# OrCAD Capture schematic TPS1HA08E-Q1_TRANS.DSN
size Custom; title: TPS1HA08E-Q1: 40-V, 8-mOhm Single-Channel Smart; rev: 1.0; note: Datasheet: SLVSDM4D     EVM: SLVUBA6; note: High-Side Switch
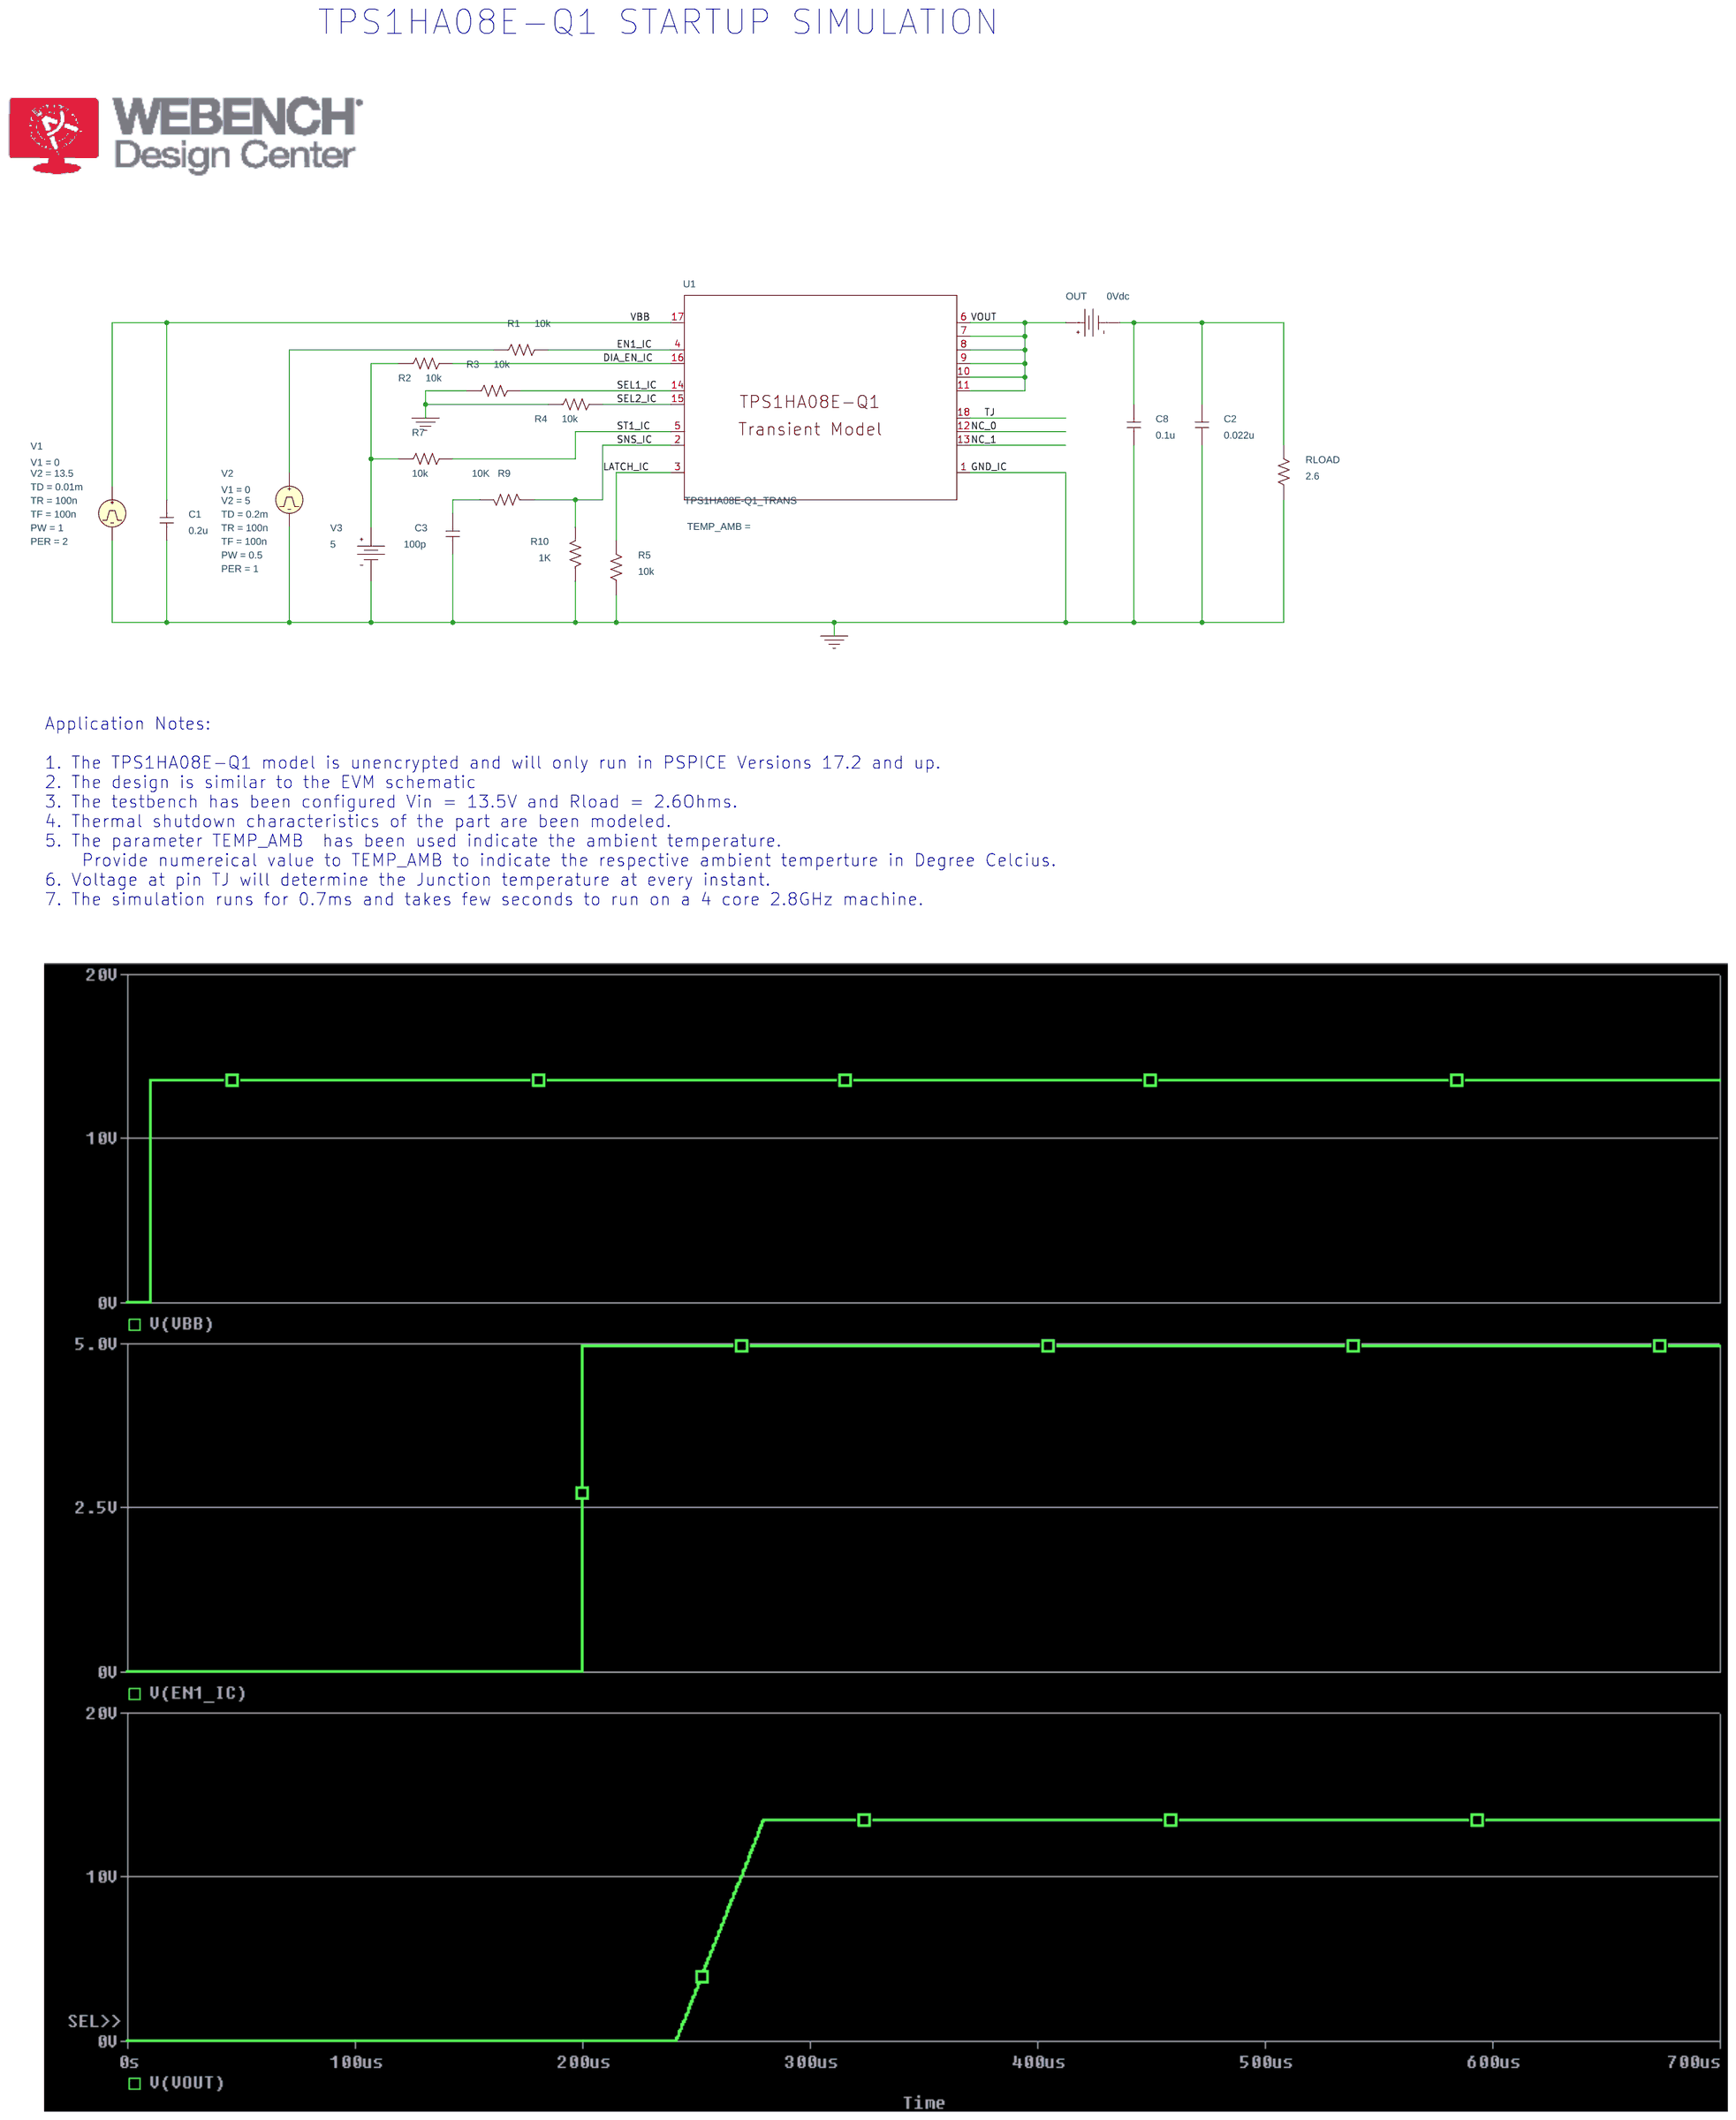
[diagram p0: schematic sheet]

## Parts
C1  0.2u  [RAD/CK05]
C2  0.022u  [RAD/CK05]
C3  100p  [RAD/CK05]
C8  0.1u  [RAD/CK05]
OUT  VDC
R1  10k  [AX/RC05]
R2  10k  [AX/RC05]
R3  10k  [AX/RC05]
R4  10k  [AX/RC05]
R5  10k  [AX/RC05]
R7  10k  [AX/RC05]
R9  10K  [AX/RC05]
R10  1K  [AX/RC05]
RLOAD  2.6  [AX/RC05]
U1  TPS1HA08E-Q1_TRANS  [PWP0016M_N]
V1  VPULSE
V2  VPULSE
V3  VDC

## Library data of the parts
C1-C3 C8 = C
OUT = VDC: DC: 0Vdc
R1-R5 R7 R9 R10 RLOAD = R
U1 = TPS1HA08E-Q1_TRANS: PSpiceTemplate: X^@REFDES  %DIA_EN %EN %GND %LATCH %NC_0 %NC_1 %SEL1 %SEL2 %SNS %ST %TJ %VBB %VOUT_0 %VOUT_1 %VOUT_2 %VOUT_3 %VOUT_4 %VOUT_5 @MODEL PARAMS: ?TEMP_AMB|TEMP_AMB=@TEMP_AMB||TEMP_AMB=25|
V1 = VPULSE: PER: 2; PW: 1; TD: 0.01m; TF: 100n; TR: 100n; V1: 0; V2: 13.5
V2 = VPULSE: PER: 1; PW: 0.5; TD: 0.2m; TF: 100n; TR: 100n; V1: 0; V2: 5
V3 = VDC: DC: 5

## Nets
0: C1.2 C2.2 C3.2 C8.2 R3.1 R4.1 R5.1 R10.1 RLOAD.1 U1.1(GND) V1.2(-) V2.2(-) V3.1(-)
DIA_EN_IC: R2.2 U1.16(DIA_EN)
EN1_IC: R1.2 U1.4(EN)
LATCH_IC: R9.1 R10.2 U1.2(SNS)
NC_0: U1.12(NC_0)
NC_1: U1.13(NC_1)
SEL1_IC: R3.2 U1.14(SEL1)
SEL2_IC: R4.2 U1.15(SEL2)
ST1_IC: R7.2 U1.5(ST)
TJ: U1.18(TJ)
VBB: C1.1 U1.17(VBB) V1.1(+)
VOUT: OUT.0(+) U1.6(VOUT_0) U1.7(VOUT_1) U1.8(VOUT_2) U1.9(VOUT_3) U1.10(VOUT_4) U1.11(VOUT_5)
N02292: C3.1 R9.2
N03618: C2.1 C8.1 OUT.1(-) RLOAD.2
N06441: R1.1 V2.1(+)
N06522: R2.1 R7.1 V3.0(+)
N07686: R5.2 U1.3(LATCH)

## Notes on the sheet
- TPS1HA08E-Q1 STARTUP SIMULATION
- Application Notes:
  1. The TPS1HA08E-Q1 model is unencrypted and will only run in PSPICE Versions 17.2 and up.
  2. The design is similar to the EVM schematic
  3. The testbench has been configured Vin = 13.5V and Rload = 2.6Ohms.
  4. Thermal shutdown characteristics of the part are been modeled.
  5. The parameter TEMP_AMB  has been used indicate the ambient temperature.
      Provide numereical value to TEMP_AMB to indicate the respective ambient temperture in Degree Celcius.
  6. Voltage at pin TJ will determine the Junction temperature at every instant.
  7. The simulation runs for 0.7ms and takes few seconds to run on a 4 core 2.8GHz machine.
